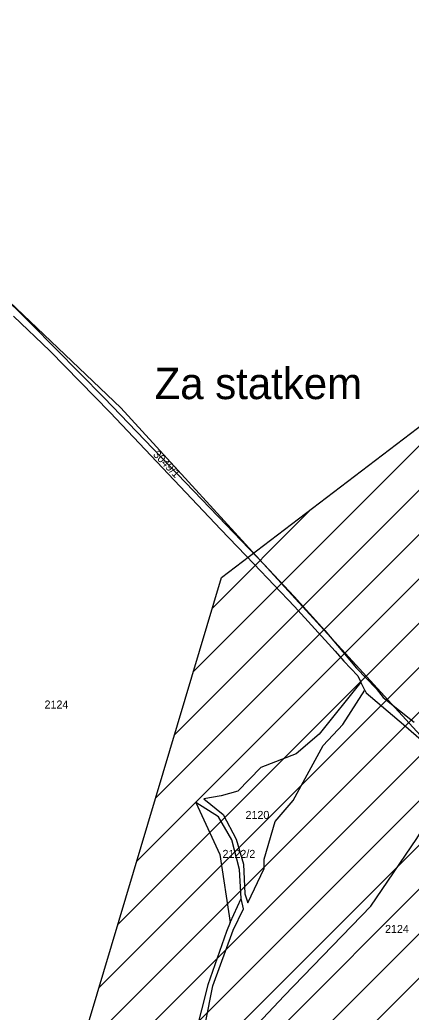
# Model space of a CAD drawing. Extents: x -564810 to -550519, y -1045831 to -1034011.
# Drawn here: x -552723 to -552473, y -1038085 to -1037452 of the extents above; entities that cross this region are included whole.
import ezdxf

# ---------------------------------------------------------------- set-up
doc = ezdxf.new("R2010")
doc.units = 0
for name, color, linetype in [('Interakční prvky', 7, 'Continuous'), ('KN stav', 7, 'Continuous'), ('Odvodněné plochy', 7, 'Continuous'), ('Parcelní čísla', 7, 'Continuous'), ('přeložka st silnice', 7, 'Continuous'), ('STG', 7, 'Continuous')]:
    doc.layers.add(name, color=color, linetype=linetype)

msp = doc.modelspace()

# ---------------------------------------------------------------- linework, layer by layer
at = {"layer": 'Interakční prvky'}
msp.add_lwpolyline([(-552827.49, -1037538.7), (-552658.27, -1037699.45), (-552453.79, -1037922.94)], dxfattribs=at)
at = {"layer": 'KN stav'}
for p, q in [((-552745.57, -1037616.22), (-552715.47, -1037645.8)), ((-552726.72, -1037641.09), (-552703.6, -1037663.08)), ((-552715.47, -1037645.8), (-552668.96, -1037692.95)), ((-552703.6, -1037663.08), (-552665.02, -1037702.44)), ((-552668.96, -1037692.95), (-552591.17, -1037774.05)), ((-552665.02, -1037702.44), (-552594.42, -1037776.97)), ((-552594.42, -1037776.97), (-552573.43, -1037798.77)), ((-552591.17, -1037774.05), (-552566.88, -1037799.3)), ((-552573.43, -1037798.77), (-552547.54, -1037826.06)), ((-552566.88, -1037799.3), (-552547.67, -1037819.57)), ((-552547.67, -1037819.57), (-552528.21, -1037841.3)), ((-552547.54, -1037826.06), (-552521.53, -1037854.55)), ((-552528.21, -1037841.3), (-552516.63, -1037854.94)), ((-552521.53, -1037854.55), (-552516.1, -1037860.91)), ((-552516.63, -1037854.94), (-552507.93, -1037865.45)), ((-552516.1, -1037860.91), (-552507.16, -1037870.18)), ((-552507.93, -1037865.45), (-552495.51, -1037878.33)), ((-552507.16, -1037870.18), (-552505.18, -1037874.33)), ((-552505.18, -1037874.33), (-552531.73, -1037907.5)), ((-552516.71, -1037901.2), (-552502.77, -1037879.36)), ((-552502.77, -1037879.36), (-552505.18, -1037874.33)), ((-552502.77, -1037879.36), (-552501.93, -1037881.11)), ((-552495.51, -1037878.33), (-552491.07, -1037883.96)), ((-552501.93, -1037881.11), (-552478.09, -1037901.31)), ((-552491.07, -1037883.96), (-552471.14, -1037899.85)), ((-552529.2, -1037914.62), (-552516.71, -1037901.2)), ((-552478.09, -1037901.31), (-552448.95, -1037926.48)), ((-552531.73, -1037907.5), (-552546.39, -1037920.05)), ((-552548.47, -1037949.75), (-552529.2, -1037914.62)), ((-552546.39, -1037920.05), (-552569.04, -1037928.61)), ((-552569.04, -1037928.61), (-552583.7, -1037943.77)), ((-552594.29, -1037946.75), (-552605.36, -1037948.57)), ((-552605.36, -1037948.57), (-552593.06, -1037958.55)), ((-552583.7, -1037943.77), (-552594.29, -1037946.75)), ((-552559.89, -1037963.13), (-552548.47, -1037949.75)), ((-552595.96, -1037960.11), (-552610.5, -1037951.01)), ((-552610.5, -1037951.01), (-552595.15, -1037984.03)), ((-552587.52, -1037974.75), (-552595.96, -1037960.11)), ((-552593.06, -1037958.55), (-552584.83, -1037974.28)), ((-552566.87, -1037987.06), (-552559.89, -1037963.13)), ((-552582.53, -1037993.7), (-552587.52, -1037974.75)), ((-552584.83, -1037974.28), (-552579.96, -1037990.27)), ((-552595.15, -1037984.03), (-552588.59, -1038027.37)), ((-552566.86, -1037992.93), (-552566.87, -1037987.06)), ((-552581.49, -1038012.09), (-552582.53, -1037993.7)), ((-552579.96, -1037990.27), (-552579.16, -1038009.1)), ((-552577.34, -1038014.92), (-552566.86, -1037992.93)), ((-552588.59, -1038027.37), (-552581.49, -1038012.09)), ((-552580.1, -1038018.64), (-552581.49, -1038012.09)), ((-552579.16, -1038009.1), (-552577.34, -1038014.92)), ((-552586.64, -1038032.35), (-552580.1, -1038018.64)), ((-552588.59, -1038027.37), (-552590.87, -1038033.15)), ((-552590.87, -1038033.15), (-552602.84, -1038067.18)), ((-552599.56, -1038067.88), (-552586.64, -1038032.35)), ((-552602.84, -1038067.18), (-552612.09, -1038103.7)), ((-552604.19, -1038091.31), (-552599.56, -1038067.88))]:
    msp.add_line(p, q, dxfattribs=at)
at = {"layer": 'Odvodněné plochy'}
msp.add_lwpolyline([(-552733.97, -1038945.29), (-552767.09, -1038873.49), (-552908.8, -1038796.18), (-552949.29, -1038879.02), (-552998.98, -1038862.45), (-553032.11, -1038794.34), (-552991.62, -1038575.28), (-552918, -1038424.33), (-552706.36, -1038183.18), (-552594.1, -1037807.66), (-552446.87, -1037695.36), (-552443.19, -1037643.82), (-552353.02, -1037531.53), (-552244.44, -1037544.42), (-552207.63, -1037586.76), (-552094.02, -1037452.14), (-552025.64, -1037519.39), (-552029.11, -1037548.28), (-552095.37, -1037603.51), (-552115.61, -1037653.21), (-551981.27, -1037719.48)], dxfattribs=at)
at = {"layer": 'přeložka st silnice'}
for p, q in [((-552672.27, -1038069.15), (-552074.48, -1037471.35)), ((-552684.33, -1038109.49), (-552060.22, -1037485.38)), ((-552696.39, -1038149.84), (-552045.96, -1037499.4)), ((-552741.55, -1038223.28), (-552031.7, -1037513.43)), ((-552624.03, -1037907.77), (-552258.96, -1037542.69)), ((-552611.97, -1037867.42), (-552284.24, -1037539.69)), ((-552636.09, -1037948.11), (-552238.84, -1037550.86)), ((-552648.15, -1037988.46), (-552225.68, -1037565.99)), ((-552660.21, -1038028.8), (-552212.53, -1037581.12)), ((-552921.51, -1038431.52), (-552096.65, -1037606.66)), ((-552948.43, -1038486.73), (-552115.14, -1037653.44)), ((-552975.36, -1038541.94), (-552096.2, -1037662.78)), ((-552994.16, -1038589.02), (-552077.26, -1037672.13)), ((-552599.91, -1037827.08), (-552536.73, -1037763.89))]:
    msp.add_line(p, q, dxfattribs=at)
at = {"layer": 'STG'}
msp.add_lwpolyline([(-552738.7, -1038346.98), (-552708.38, -1038265.2), (-552690.01, -1038230.29), (-552643.17, -1038169.65), (-552598.16, -1038120.95), (-552554.07, -1038074.09), (-552498.95, -1038017.13), (-552469.56, -1037973.94), (-552440.17, -1037926.17), (-552408.94, -1037830.61)], dxfattribs=at)

# ---------------------------------------------------------------- texts
at = {"layer": 'Parcelní čísla'}
for s, height, p in [('Za statkem', 20, (-552636.73, -1037693.87)), ('2124', 5.1, (-552706.89, -1037891.06)), ('2120', 5.1, (-552578.75, -1037961.44)), ('2122/2', 5.1, (-552593.42, -1037986.27)), ('2124', 5.1, (-552489.8, -1038034.12))]:
    msp.add_text(s, height=height, dxfattribs=at).set_placement(p)
msp.add_text('3049/1', height=5.1, rotation=314.3717, dxfattribs=at).set_placement((-552638.09, -1037729.55))

doc.saveas('drawing.dxf')
